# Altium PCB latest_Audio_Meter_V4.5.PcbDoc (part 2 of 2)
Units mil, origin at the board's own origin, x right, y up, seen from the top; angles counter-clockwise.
Board outline 2756.14 x 2519.69 mil, 2 copper layers (Top Layer, Bottom Layer), stack 57.087 mil thick; 115 components, 61 nets, 352 pads, 1177 vias.
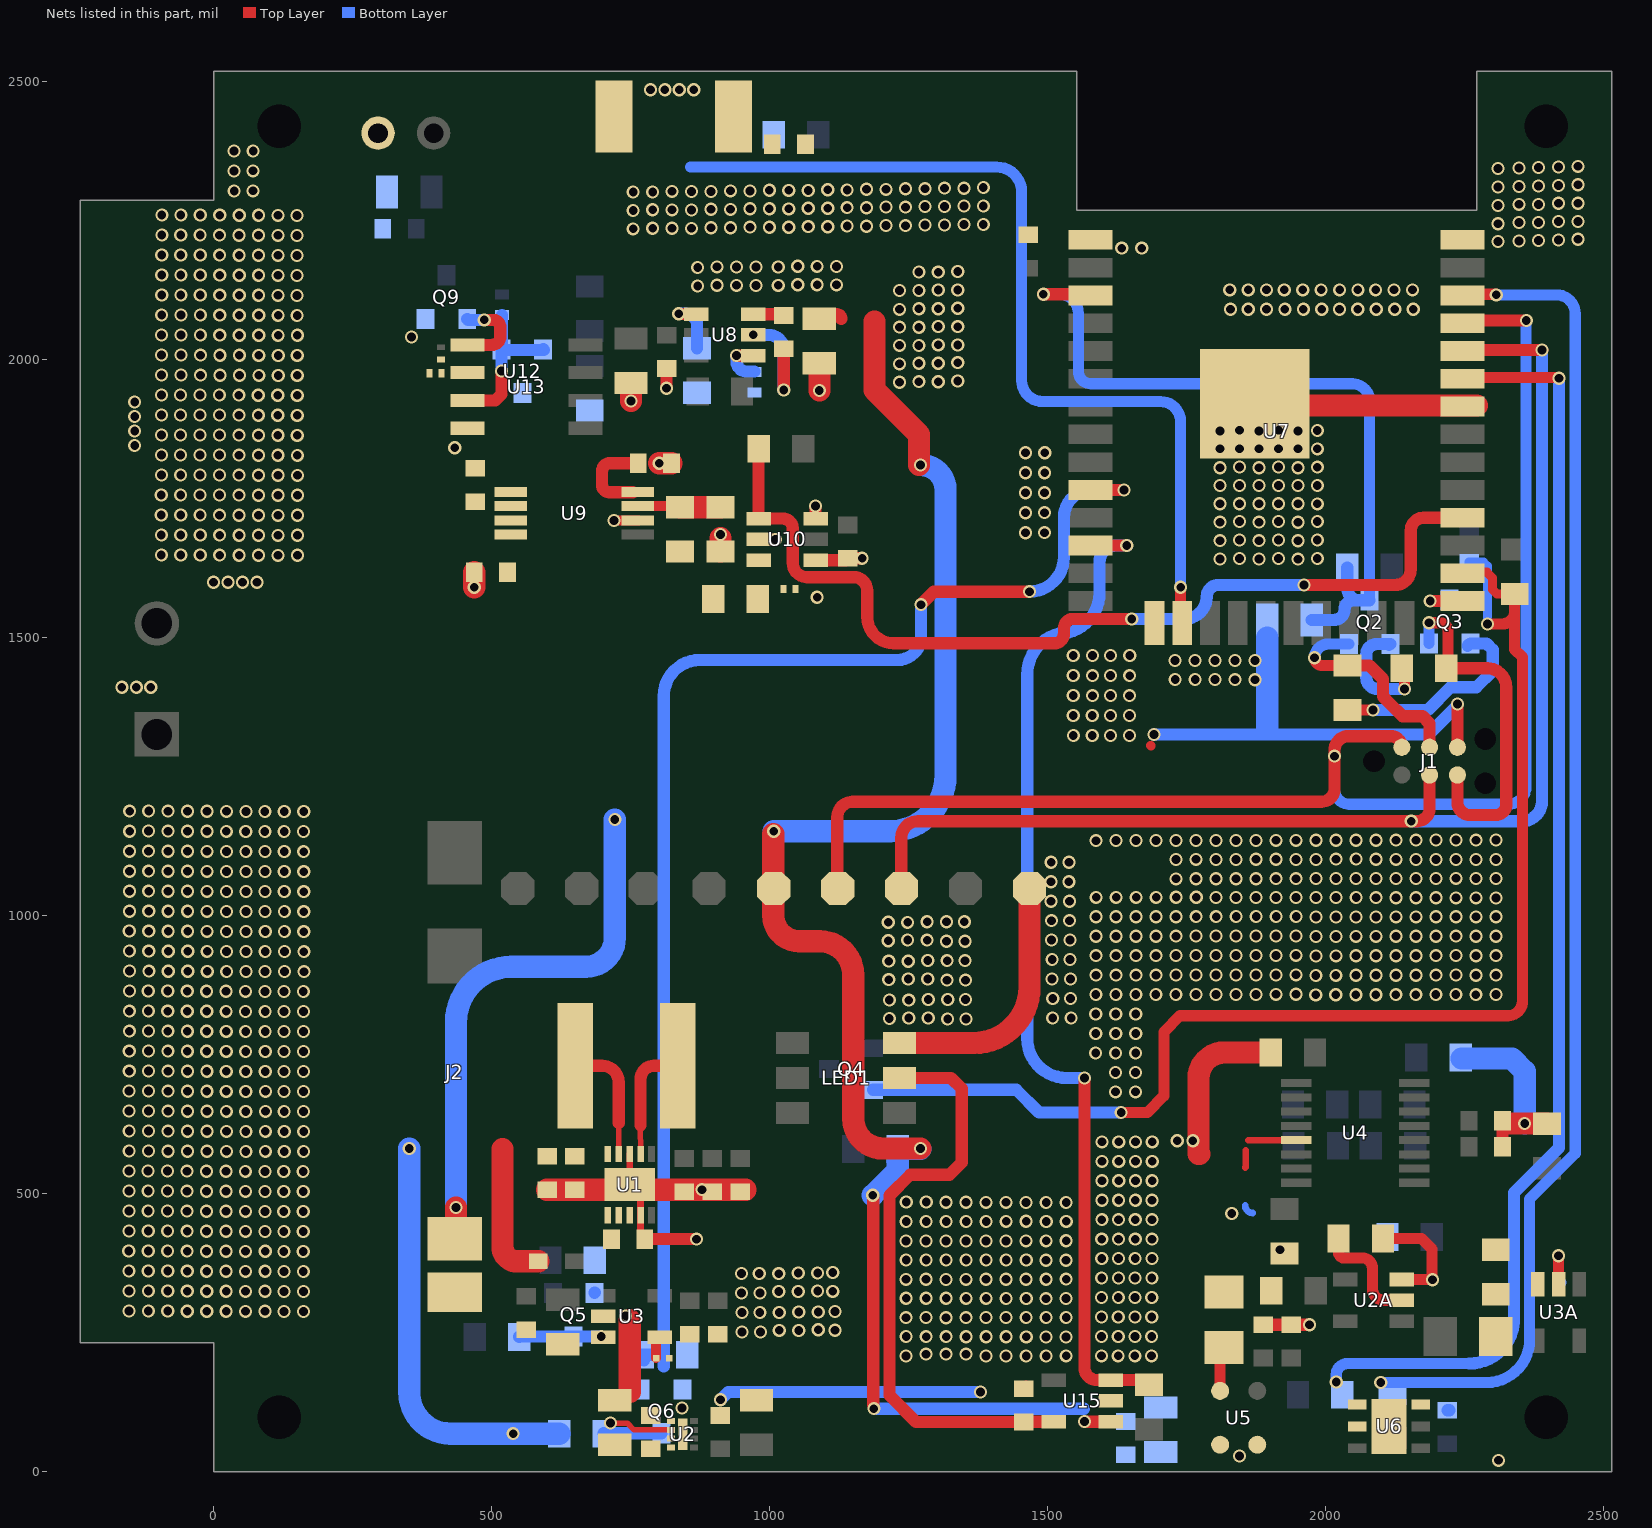
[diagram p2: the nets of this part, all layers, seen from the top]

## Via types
v1: diameter 23.62, hole 15.75, Top Layer to Bottom Layer, 917 vias
v2: diameter 23.62, hole 15.75, Top Layer to Bottom Layer, tented both sides, 260 vias

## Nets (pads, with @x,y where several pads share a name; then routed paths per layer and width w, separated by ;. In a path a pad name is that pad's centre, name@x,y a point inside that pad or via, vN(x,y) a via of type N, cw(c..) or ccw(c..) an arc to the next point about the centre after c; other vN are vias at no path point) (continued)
CLED#: C76.2 Q4.2 R56.2 U7.26 | length 2418
  Top Layer w8: R56.2@2323,1579 R56.2@2341,1579
  Top Layer w12: R56.2@2323,1579 R56.2@2323,1588
  Top Layer w16: U7.26@2242,1618 2291,1618 2301,1608 2301,1587 2309,1579 R56.2@2323,1579
  Top Layer w20: v1(1633,646) 1680,646 1710,676 1710,791 1739,820 2329,820 ccw(c2329,846) 2355,846 2355,1465 2341,1479 2341,1546.94 ; U7.26@2242,1618 ccw(c2243,1618) U7.26@2243,1617 ; v1(2292,1525) 2319.06,1525 ccw(c2319.06,1546.94) 2341,1546.94 ; R56.2@2341,1579 2341,1546.94
  Bottom Layer w16: C76.2@2259,1636 2285,1636 2292,1629 v1(2292,1525)
  Bottom Layer w22: Q4.2@1186.37,686.6 1444.4,686.6 1485,646 v1(1633,646)
DTR: J1.5 Q3.2 RC2.2 | length 644.9
  Top Layer w20: v1(2187,1527) 2206.76,1527 cw(c2206.76,1512.76) 2221,1512.76 RC2.2@2221,1447
  Top Layer w22: RC2.2@2218,1445 2291.86,1445 cw(c2291.86,1410.86) 2326,1410.86 2326,1200.35 cw(c2306.65,1200.35) 2306.65,1181 2260.94,1181 cw(c2260.94,1203.94) 2238,1203.94 J1.5@2238,1253
  Bottom Layer w20: Q3.2@2186.6,1489.63 2186.6,1527 v1(2187,1527)
EN#: Q6.3 R4#.1 U2.6 | length 224.2
  Top Layer w10: v1@710.88,86.12 710,87 v1(714,87) 744.31,87 756.44,74.87 U2.6@823.33,74.87
  Bottom Layer w10: R4#.1@702,68 R4#.1@702,68.63
  Bottom Layer w22: R4#.1@702,68.63 Q6.3@806,68.63
ENABLE: C78.1 Q2.3 R43.1 U7.3 | length 1374.9
  Top Layer w22: v1(1493,2118) U7.3@1572.71,2118
  Bottom Layer w20: v1(1493,2118) 1522.14,2118 cw(c1522.14,2084.14) 1556,2084.14 1556,1979.94 ccw(c1578.94,1979.94) 1578.94,1957 2049,1957 cw(c2049,1926) 2080,1926 Q2.3@2080,1567.37 ; 2012,1532 2015.9,1532
  Bottom Layer w22: C78.1@1976,1532 2012,1532 ; 2015.9,1532 ccw(c2015.9,1551.1) 2035,1551.1 cw(c2051.27,1551.1) 2051.27,1567.37 2060.94,1567.37 ; R43.1@2040,1626.44 2040,1588.31 ccw(c2060.94,1588.31) 2060.94,1567.37 ; Q2.3@2080,1567.37 2060.94,1567.37
GND: C1.2 C2.2 C3.2 C4.2 C7.2 C10.2 C11.2 C12.2 C13.2 C16.2 C17.2 C18.2 C19.2 C22.2 C25.2 C26.2 C27.2 C28.2 C29.2 C33.2 C34.2 C35.2 C37.2 C38.2 C40.2 C41.2 C78.2 C79.2 C80.2 C81.2 C82.2 C85.2 C#3.2 C#4.2 C#5.2 J1.6 J2.4 J5.2 LED1.6 P5.1 pad.MH2 pad.MH3 Q5.2 Q6.2 R3.2 R8.1 R10.1 R12.1 R14.1 R28.1 R29.1 R32.2 R33.2 R35.2 R36.2 R38.1 R39.2 R42.2 SW2.2 U1.3 U1.9 U1.11 U2.5 U2.9 U2A.2 U3.2 U3A.2 U4.5 U5.2 U5.3 U6.2 U6.7 U7.1 U7.15 U7.32 U7.38 U7.39 U8.5 U9.2 U9.5 U10.2 U10.4 U10.6 U12.3 U13.4 U15.2 | length 4682.1
  Top Layer w12: U1.3@748.63,571.24 748.63,532.37 768.31,512.69 768.31,507 U1.11@768.31,503 ; C10.2@768.31,420.69 U1.9@768.31,461 U1.11@768.31,502 ; 1856,547 ccw(c1856,548) 1857,548 1857,578 ; 1862,596.2 U4.5@1947.75,596.2 ; v1@2353.05,626 ccw(c2334,637) v1@2356,637
  Top Layer w16: 1686,1306 cw(c1686,1305) 1687,1305
  Top Layer w18: v1(720.44,1711) U9.2@764.97,1711
  Top Layer w20: R3.2@2024,419 2024,395 ccw(c2035,395) 2035,384 2067,384 cw(c2067,366) 2085,366 2085,329 ccw(c2106,329) 2106,308 U2A.2@2138.18,308 ; U3A.2@2420,337.18 v1(2420,388)
  Top Layer w22: U1.11@763.31,507 ccw(c767.31,507) 767.31,503 U1.11@768.21,503 ; U1.11@768.31,502 ccw(c763.31,502) U1.11@768.21,503 ; U1.11@768.31,503 U1.11@768.21,503 ; C10.2@773,418 C10.2@776,418 v1(869,418) ; v1(815,1949) C17.2@815,1984.57 ; C12.2@896,502 cw(c897,502) C12.2@897,503 ; C37.2@905,245 cw(c907,245) C37.2@907,247 ; v1(971.18,2045) U8.5@980.85,2045 ; U10.2@980.82,1677 v1(1011,1677) ; v1(1026,1946) C19.2@1026,2020 ; v1(1083,1737) 1083.18,1736.82 U10.6@1083.18,1714.4 ; U10.4@1083.18,1639.6 1137.6,1639.6 ccw(c1137.6,1643) C85.2@1141,1643 v1@1164,1643 ; C#3.2@1458,149 C#3.2@1462.02,153.02 ; C3.2@1889,264 C4.2@1939,264 v1(1972,264) ; U6.7@2115,46.77 U6.7@2115,81 ; J1.6@2238,1303 v1(2238,1381) ; C1.2@2319,584 C2.2@2319,631
  Top Layer w40: v1(469,1591) C79.2@469,1618 ; C11.2@600,507 C40.2@650,507 U1.11@763.31,507 ; C27.2@749,143 v1@749,272 ; v1(751,1926) C16.2@751,1958.57 ; U1.11@768.31,507 v1(879,507) C13.2@957,507 ; v1(802,1814) R39.2@824,1814 ; R38.1@912,1655 v1@912,1679 ; v1(1090,1945) C18.2@1090,1994 ; LED1.6@1234.46,770.99 1368,770.99 ccw(c1368,870.99) 1468,870.99 P5.1@1468,1049 ; 1774,571 cw(c1774,573) 1772,573 1772,707 cw(c1819,707) 1819,754 R8.1@1902,754 ; U7.39@1868.35,1923.31 ccw(c1873.67,1923.31) 1873.67,1918 U7.32@2273,1918 ; C2.2@2324,626 2353.05,626 v1(2359,626) R12.1@2399,626
  Bottom Layer w12: 1856,479 ccw(c1870,479) 1870,465
  Bottom Layer w20: 2420,344 ccw(c2424,344) 2424,340
  Bottom Layer w22: Q5.2@685.4,321.37 Q5.2@686,321.97 ; v1(912,129) 926,143 v1(1380,143) ; v1(971.18,2045) 998.77,2045 cw(c998.77,2017.78) 1026,2017.78 v1(1026,1946) ; v1(1692,1326) 2186,1326 2238,1378 v1(2238,1381) ; C7.2@2220,110 C7.2@2224,110 ; R10.1@2244,745 ccw(c2246,745) R10.1@2246,743
  Bottom Layer w40: 1896,1337 1896,1500 ; R10.1@2246,743 2336,743 2359,720 v1(2359,626)
  other v1: 2312,20 1846,28 843,114 1246.02,207.67 1390.02,207.79 1426.02,207.79 1462.02,207.9 1498.02,207.9 1534.02,208.01 1597.44,208 1627.55,208 1657.66,208 1687.77,208 1282,211 1318,211 1354,211 1354.13,242.45 1390.13,242.45 1426.13,242.34 1462.13,242.23 1497.9,241.89 1533.9,242.01 1246.13,242.67 1282.13,242.56 1318.13,242.56 1597.55,243 1627.66,243 1657.77,243 1687.89,243 950.78,251 984,251 1017.89,253.89 1052.89,253.78 1118,254 1087.89,254.89 1246.01,276.67 1282.01,276.78 1318.01,276.56 1354.01,276.67 1390.01,276.78 1426.01,276.78 1462.01,276.89 1498.01,276.89 1534.01,277.01 1597.66,278 1627.77,278 1657.89,278 1688,278 741,280 950.89,286 982.89,286 1017.89,285.89 1052.89,287 1087.89,286.89 1118,288 1354.12,311.45 1390.12,311.45 1426.12,311.34 1462.12,311.23 1497.89,310.89 1533.89,311 1246.12,311.67 1282.12,311.56 1318.12,311.56 1597.77,313 1627.89,313 1658,313 1688.11,313 949.78,321 983,321 1016.89,323.89 1051.89,323.78 1114,324 1086.89,324.89 1246.01,345.67 1282.01,345.78 1318.01,345.56 1354.01,345.67 1390.01,345.78 1426.01,345.78 1462.01,345.89 1498.01,345.89 1534.01,346 1597.89,348 1628,348 1658.11,348 1688.22,348 949.89,356 981.89,356 1016.89,355.89 1051.89,357 1086.89,356.89 1114,358 1354.12,380.45 1390.12,380.45 1426.12,380.33 1462.12,380.22 1497.89,379.89 1533.89,380 1246.12,380.67 1282.12,380.56 1318.12,380.56 1598,383 1628.11,383 1658.22,383 1688.33,383 1919,399 1246,414.67 1282,414.78 1318,414.55 1354,414.67 1390,414.78 1426,414.78 1462,414.89 1498,414.89 1534,415 1598.11,418 1628.22,418 1658.33,418 1688.44,418 1246.11,449.67 1282.11,449.78 1318.11,449.78 1354.11,449.89 1390.11,449.89 1426.11,450 1462.11,450.11 1498.11,449.89 1534.11,450 1598.22,453 1628.33,453 1658.44,453 1688.55,453 1832,464 1317.99,484.44 1353.99,484.33 1389.99,484.22 1425.99,484.22 1461.99,484.11 1497.99,484.11 1533.99,484 1246.22,484.67 1282.22,484.78 1598.33,488 1628.44,488 1658.55,488 1688.67,488 1598.44,523 1628.55,523 1658.67,523 1688.78,523 1598.55,558 1628.67,558 1658.78,558 1688.89,558 1598.67,593 1628.78,593 1658.89,593 1689,593 1734,595 1762,595 1622.89,683 1658.89,683 1623,718 1659,718 1587.11,753 1623.11,753 1659.11,753 1587.22,788 1623.22,788 1659.22,788 1320.78,814 1354,814 1215.89,814.89 1250.89,816 1285.89,815.89 1509.78,816 1543,816 1587.33,823 1623.33,823 1659.33,823 1215.89,848.11 1250.89,848 1285.89,849.11 1320.89,849 1352.89,849 1509.89,851 1541.89,851 1587.44,858 1623.44,858 1659.44,858 1695.44,858 1731.44,858.11 1767.44,858.22 1803.44,858.22 1839.44,858.33 1875.44,858.33 1911.44,858.45 1983.22,857.55 2019.22,857.67 2055.22,857.78 2091.22,857.78 2127.22,857.89 2163.22,857.89 2199.22,858 2235.22,858.11 2271.22,857.89 2307.22,858 1947.44,858.56 1319.78,884 1353,884 1214.89,884.89 1249.89,886 1284.89,885.89 1508.78,886 1542,886 1587.55,893 1623.55,893 1659.55,893 1695.55,893 1731.55,893.11 1767.55,893.22 1803.55,893.22 1839.55,893.33 1875.55,893.33 1911.55,893.45 1983.33,892.55 2019.33,892.67 2055.33,892.78 2091.33,892.78 2127.33,892.89 2163.33,892.89 2199.33,893 2235.33,893.11 2271.33,892.89 2307.33,893 1947.55,893.56 1214.89,918.11 1249.89,918 1284.89,919.11 1319.89,919 1351.89,919 1508.89,921 1540.89,921 1587.67,928 1623.67,928 1659.67,928 1695.67,928 1731.67,928.11 1767.67,928.22 1803.67,928.22 1839.67,928.33 1875.67,928.33 1911.67,928.45 1983.44,927.55 2019.44,927.67 2055.44,927.78 2091.44,927.78 2127.44,927.89 2163.44,927.89 2199.44,928 2235.44,928.11 2271.44,927.89 2307.44,928 1947.67,928.56 1318.78,954 1352,954 1213.89,954.89 1248.89,956 1283.89,955.89 1507.78,956 1541,956 1587.78,963 1623.78,963 1659.78,963 1695.78,963 1731.78,963.11 1767.78,963.22 1803.78,963.22 1839.78,963.33 1875.78,963.33 1911.78,963.45 1983.55,962.55 2019.55,962.67 2055.55,962.78 2091.55,962.78 2127.55,962.89 2163.55,962.89 2199.55,963 2235.55,963.11 2271.55,962.89 2307.55,963 1947.78,963.56 1213.89,988.11 1248.89,988 1283.89,989.11 1318.89,989 1350.89,989 1507.89,991 1539.89,991 1587.89,998 1623.89,998 1659.89,998 1695.89,998 1731.89,998.11 1767.89,998.22 1803.89,998.22 1839.89,998.33 1875.89,998.33 1911.89,998.45 1983.66,997.55 2019.66,997.67 2055.66,997.78 2091.66,997.78 2127.66,997.89 2163.66,997.89 2199.66,998 2235.66,998.11 2271.66,997.89 2307.66,998 1947.89,998.56 1506.78,1026 1540,1026 2091.54,1032.44 2127.54,1032.33 2163.54,1032.22 2199.54,1032.22 2235.54,1032.11 2271.54,1032.11 2307.54,1032 1588,1033 1624,1033 1660,1033 1696,1033 1732,1033.11 1768,1033.22 1803.77,1032.89 1839.77,1032.78 1875.77,1032.67 1911.77,1032.67 1947.77,1032.55 1983.77,1032.55 2019.77,1032.67 2055.77,1032.78 1506.89,1061 1538.89,1061 1731.66,1066.22 1767.66,1066.33 1803.66,1066.33 1839.66,1066.44 1875.66,1066.44 1911.66,1066.55 1947.66,1066.55 1983.66,1066.66 2019.66,1066.66 2055.66,1066.77 2091.66,1066.77 2127.66,1066.89 2163.66,1066.89 2199.66,1067 2235.66,1067.11 2271.66,1066.89 2307.66,1067 1507,1096 1539,1096 1731.77,1101.22 1767.77,1101.33 1803.54,1100.99 1839.54,1100.88 1875.77,1101.44 1947.54,1101.22 1983.54,1101.11 2091.54,1101.44 2127.54,1101.33 2163.54,1101.22 2199.54,1101.22 2235.54,1101.11 2271.54,1101.11 2307.54,1100.99 1911.77,1101.55 2019.77,1101.66 2055.77,1101.77 1587.65,1134.99 1623.65,1135.1 1659.65,1135.1 1695.65,1135.22 1731.65,1135.22 1767.65,1135.33 1803.65,1135.33 1839.65,1135.44 1875.65,1135.44 1911.65,1135.55 1947.65,1135.55 1983.65,1135.66 2019.65,1135.66 2055.65,1135.77 2091.65,1135.77 2127.65,1135.88 2163.65,1135.88 2199.65,1135.99 2235.65,1136.11 2271.65,1135.88 2307.65,1135.99 1547,1324 1581,1324.12 1614,1324 1648,1324.12 1546.89,1360 1580.89,1360.12 1613.89,1360 1647.89,1360.12 1546.89,1396 1581.22,1395.89 1613.89,1396 1648.22,1395.89 -165,1411 -139,1411 -113,1411 1730.12,1425 1766.12,1425.11 1801.89,1424.78 1837.89,1424.67 1873.89,1424.56 1546.78,1432 1581.33,1431.89 1613.78,1432 1648.33,1431.89 1730,1459 1766,1459.11 1802,1459.11 1838,1459.22 1874,1459.22 1546.78,1468 1581.44,1467.89 1613.78,1468 1648.44,1467.89 1086,1573 0,1600 26,1600 52,1600 78,1600 1951,1641.44 1811,1641.55 1881,1641.55 1167,1643 1846,1642.67 1916,1642.67 1986,1642.55 81,1648.44 116,1648.33 151,1648.44 -94,1649 -59,1648.89 -24,1648.78 11,1648.67 46,1648.55 1811,1674.78 1881,1674.78 1951,1674.67 1846,1675.89 1916,1675.89 1986,1675.78 81,1684.44 116,1684.33 151,1684.44 -94,1685 -59,1684.89 -24,1684.78 11,1684.67 46,1684.55 912,1686 1461,1689 1495,1689.12 1811,1708 1881,1708 1951,1707.89 1846,1709.11 1916,1709.11 1986,1709 80.89,1720.44 115.89,1720.33 151.11,1720.44 -94.11,1721 -59.11,1720.89 -24.11,1720.78 10.89,1720.67 45.89,1720.55 1460.89,1725 1494.89,1725.12 1811,1741.22 1846,1741.11 1881,1741.22 1916,1741.11 1951,1741.11 1986,1741 80.78,1756.44 115.78,1756.33 151.22,1756.44 -94.22,1757 -59.22,1756.89 -24.22,1756.78 10.78,1756.67 45.78,1756.55 1460.89,1761 1495.22,1760.89 1811,1774 1846,1773.89 1881,1774 1916,1773.89 1951,1773.89 1986,1773.78 80.78,1792.44 115.78,1792.33 150.89,1792.22 -93.89,1792.77 -59.22,1792.89 -24.22,1792.78 10.78,1792.67 45.78,1792.55 1460.78,1797 1495.33,1796.89 1811,1806 1881,1806 1951,1805.89 1846,1807.11 1916,1807.11 1986,1807 80.67,1828.44 115.67,1828.33 150.78,1828.22 -93.78,1828.77 -59.33,1828.89 -24.33,1828.78 10.67,1828.67 45.67,1828.55 1460.78,1833 1495.44,1832.89 1811,1840.13 1846,1840.02 1881,1840.13 1916,1840.02 1951,1840.02 1986,1839.91 434,1842 -142,1846 80.67,1864.44 115.67,1864.33 150.67,1864.22 -93.67,1864.77 -59.33,1864.89 -24.33,1864.78 10.67,1864.67 45.67,1864.55 -142,1872 1811,1872.13 1881,1872.13 1951,1872.02 1846,1873.24 1916,1873.24 1986,1873.13 -142,1898 80.55,1900.44 115.55,1900.33 150.67,1900.22 -93.67,1900.77 -59.45,1900.89 -24.45,1900.78 10.55,1900.67 45.55,1900.55 -142,1924 80.44,1936.44 115.44,1936.33 150.55,1936.22 -93.55,1936.77 -59.56,1936.89 -24.56,1936.78 10.44,1936.67 45.44,1936.55 1234,1959.67 1269,1960.78 1304,1960.67 1339,1961.78 11.45,1972.44 46.45,1972.33 81.45,1972.22 116.45,1972.1 150.55,1972.22 -93.55,1972.77 -58.55,1972.66 -23.55,1972.55 1234,1992.89 1269,1994 1304,1993.89 1339,1995 11.33,2008.44 46.33,2008.33 81.33,2008.22 116.33,2008.1 150.67,2008.22 -93.67,2008.77 -58.67,2008.66 -23.67,2008.55 1234,2026.11 1269,2026 1304,2027.11 1339,2027 11.22,2044.44 46.22,2044.33 81.22,2044.22 116.22,2044.1 150.78,2044.22 -93.78,2044.77 -58.78,2044.66 -23.78,2044.55 1234,2058.89 1269,2058.78 1304,2059.89 1339,2059.78 11.22,2080.44 46.22,2080.33 81.22,2080.22 116.22,2080.1 150.44,2079.99 -93.44,2080.54 -58.78,2080.66 -23.78,2080.55 1234,2090.89 1829.55,2091 1861.55,2091 1894.33,2091 1927.55,2091 1960.78,2091 1994,2091 2026,2091 2058.78,2091 2092,2091 2125.22,2091 2158.45,2091 1269,2092 1304,2091.89 1339,2093 11.11,2116.44 46.11,2116.33 81.11,2116.22 116.11,2116.1 150.33,2115.99 -93.33,2116.54 -58.89,2116.66 -23.89,2116.55 1234,2124.89 1269,2124.78 1304,2125.89 1339,2125.78 1828.44,2126 1861.67,2126 1894.44,2126 1926.44,2126 1959.67,2126 1992.89,2126 2026.11,2126 2058.89,2126 2090.89,2126 2124.11,2126 2157.33,2126 871,2133.11 906,2134.22 941,2134.11 976,2134 1016,2134.11 1051,2135.22 1086,2135.11 1121,2135 11.11,2152.44 46.11,2152.33 81.11,2152.22 116.11,2152.1 150.22,2151.99 -93.22,2152.54 -58.89,2152.66 -23.89,2152.55 1269,2158 1304,2157.89 1339,2159 871,2166.33 906,2167.45 941,2167.33 976,2167.22 1016,2167.33 1051,2168.45 1086,2168.33 1121,2168.22 11,2188.44 46,2188.33 81,2188.22 116,2188.1 150.22,2187.99 -93.22,2188.54 -59,2188.66 -24,2188.55 1634,2201 1670,2201 2311,2213 2349,2213.89 2384,2215 2420,2215.89 2455,2217 10.89,2224.44 45.89,2224.33 80.89,2224.22 115.89,2224.1 150.11,2223.99 -93.11,2224.54 -59.11,2224.66 -24.11,2224.55 755,2235.78 790,2236.89 825,2236.78 860,2236.67 895,2237.78 930,2237.67 965,2238.78 1000,2238.67 1035,2238.55 1070,2239.67 1105,2239.55 1140,2240.67 1175,2240.55 1210,2241.67 1245,2241.55 1280,2242.67 1315,2242.55 1350,2243.67 1385,2243.55 2311,2245 2349,2247.11 2384,2247 2420,2249.11 2455,2249 11.11,2260.44 46.11,2260.33 81.11,2260.22 116.11,2260.1 150.11,2259.99 -93.11,2260.54 -58.89,2260.66 -23.89,2260.55 755,2269 790,2270.11 825,2270 860,2269.89 895,2271 930,2270.89 965,2272 1000,2271.89 1035,2271.78 1070,2272.89 1105,2272.78 1140,2273.89 1175,2273.78 1210,2274.89 1245,2274.78 1280,2275.89 1315,2275.78 1350,2276.89 1385,2276.78 2311,2277.78 2349,2279.89 2384,2279.78 2420,2281.89 2455,2281.78 755,2302.22 790,2302.11 825,2303.22 860,2303.11 895,2303 37,2304 71,2304.12 930,2304.11 965,2304 1000,2305.11 1035,2305 1070,2304.89 1105,2306 1140,2305.89 1175,2307 1210,2306.89 1245,2308 1280,2307.89 1315,2309 1350,2308.89 1385,2310 2311,2311 2349,2311.89 2384,2313 2420,2313.89 2455,2315 36.89,2340 70.89,2340.12 2311,2344.22 2349,2345.11 2384,2346.22 2420,2347.11 2455,2348.22 36.89,2376 71.22,2375.89
  other v2: -82.34,288.46 -47.34,288.35 -12.34,288.24 22.66,288.13 57.66,288.02 92.66,288.13 126.66,287.79 161.66,287.68 -152.34,288.68 -117.34,288.57 -82.34,324.46 -47.34,324.35 -12.34,324.24 22.66,324.13 57.66,324.02 92.66,324.13 126.66,323.79 161.66,323.68 -152.34,324.68 -117.34,324.57 -82.45,360.46 -47.45,360.35 -12.45,360.24 22.55,360.13 57.55,360.02 92.77,360.13 126.55,359.79 161.55,359.68 -152.45,360.68 -117.45,360.57 -82.56,396.46 -47.56,396.35 -12.56,396.24 22.44,396.13 57.44,396.02 92.89,396.13 126.44,395.79 161.44,395.68 -152.56,396.68 -117.56,396.57 -152.23,432.46 -82.56,432.46 -47.56,432.35 -12.56,432.24 22.44,432.13 57.44,432.02 92.55,431.9 126.44,431.79 161.44,431.68 -117.56,432.57 -152.11,468.46 -82.67,468.46 -47.67,468.35 -12.67,468.24 22.33,468.13 57.33,468.02 92.44,467.9 126.33,467.79 161.33,467.68 -117.67,468.57 -152,504.46 -82.67,504.46 -47.67,504.35 -12.67,504.24 22.33,504.13 57.33,504.02 92.33,503.9 126.33,503.79 161.33,503.68 -117.67,504.57 -152,540.46 -82.78,540.46 -47.78,540.35 -12.78,540.24 22.22,540.13 57.22,540.02 92.33,539.9 126.22,539.79 161.22,539.68 -117.78,540.57 162.11,575.45 -151.89,576.46 -116.89,576.34 -81.89,576.23 -46.89,576.12 -11.89,576.01 23.11,575.9 58.11,575.79 93.11,575.9 127.11,575.56 162.11,611.45 -151.89,612.46 -116.89,612.34 -81.89,612.23 -46.89,612.12 -11.89,612.01 23.11,611.9 58.11,611.79 93.11,611.9 127.11,611.56 161.99,647.45 -152,648.46 -117,648.34 -82,648.23 -47,648.12 -12,648.01 23,647.9 58,647.79 93.22,647.9 126.99,647.56 161.88,683.45 -152.11,684.46 -117.11,684.34 -82.11,684.23 -47.11,684.12 -12.11,684.01 22.89,683.9 57.89,683.79 93.33,683.9 126.88,683.56 161.88,719.45 -151.78,720.23 -117.11,720.34 -82.11,720.23 -47.11,720.12 -12.11,720.01 22.89,719.9 57.89,719.79 93,719.67 126.88,719.56 161.77,755.45 -151.67,756.23 -117.23,756.34 -82.23,756.23 -47.23,756.12 -12.23,756.01 22.77,755.9 57.77,755.79 92.89,755.67 126.77,755.56 161.77,791.45 -151.56,792.23 -117.23,792.34 -82.23,792.23 -47.23,792.12 -12.23,792.01 22.77,791.9 57.77,791.79 92.77,791.67 126.77,791.56 161.66,827.45 -151.56,828.23 -117.34,828.34 -82.34,828.23 -47.34,828.12 -12.34,828.01 22.66,827.9 57.66,827.79 92.77,827.67 126.66,827.56 161.55,863.45 -151.45,864.23 -117.45,864.34 -82.45,864.23 -47.45,864.12 -12.45,864.01 22.55,863.9 57.55,863.79 92.66,863.67 126.55,863.56 127.55,899.33 162.55,899.22 -151.45,900.23 -116.45,900.12 -81.45,900.01 -46.45,899.89 -11.45,899.78 23.55,899.67 58.55,899.56 92.66,899.67 127.44,935.33 162.44,935.22 -151.56,936.23 -116.56,936.12 -81.56,936.01 -46.56,935.89 -11.56,935.78 23.44,935.67 58.44,935.56 92.77,935.67 127.33,971.33 162.33,971.22 -151.67,972.23 -116.67,972.12 -81.67,972.01 -46.67,971.89 -11.67,971.78 23.33,971.67 58.33,971.56 92.89,971.67 92.55,1007.44 127.33,1007.33 162.33,1007.22 -151.33,1008 -116.67,1008.12 -81.67,1008.01 -46.67,1007.89 -11.67,1007.78 23.33,1007.67 58.33,1007.56 92.44,1043.44 127.22,1043.33 162.22,1043.22 -151.22,1044 -116.78,1044.12 -81.78,1044.01 -46.78,1043.89 -11.78,1043.78 23.22,1043.67 58.22,1043.56 92.33,1079.44 127.22,1079.33 162.22,1079.22 -151.11,1080 -116.78,1080.12 -81.78,1080.01 -46.78,1079.89 -11.78,1079.78 23.22,1079.67 58.22,1079.56 92.33,1115.44 127.11,1115.33 162.11,1115.22 -151.11,1116 -116.89,1116.12 -81.89,1116.01 -46.89,1115.89 -11.89,1115.78 23.11,1115.67 58.11,1115.56 92.22,1151.44 126.99,1151.33 161.99,1151.22 -151,1152 -117,1152.12 -82,1152.01 -47,1151.89 -12,1151.78 23,1151.67 58,1151.56 92.22,1187.44 127.22,1187.33 162.22,1187.22 -151,1188 -116.78,1188.12 -81.78,1188.01 -46.78,1187.89 -11.78,1187.78 23.22,1187.67 58.22,1187.56
ILIM#: R39.1 U9.4 | length 160.7
  Top Layer w22: U9.4@754.12,1762 712,1762 cw(c712,1775) 699,1775 699,1800.34 cw(c712.66,1800.34) 712.66,1814 R39.1@764,1814
IN+: R30.1 U12.1 U12.2 U13.3 | length 286.9
  Top Layer w22: U13.3@456.7,1927 507,1927 518,1938 v1(518,1980)
  Bottom Layer w22: v1(518,1980) 518.2,1980.2 U12.1@518.2,2019 ; R30.1@519,2081 519,2019.8 U12.1@518.2,2019 ; U12.2@593,2019 594,2018 519.2,2018 U12.1@518.2,2019
IN-: R31.1 R32.1 U13.2 | length 2
  Top Layer w12: U13.2@456.7,1977 U13.2@458.7,1977
IO_0: Q3.3 U7.25 | length 104.5
  Top Layer w20: U7.25@2242,1568 2244,1566 U7.25@2249,1561
  Top Layer w22: v1(2189,1566) 2244,1566 U7.25@2247.29,1566
  Bottom Layer w22: v1(2189,1566) 2221.63,1566 ccw(c2221.63,1568.37) Q3.3@2224,1568.37
ISET: R28.2 U8.4 | length 83.5
  Top Layer w22: v1@941,2007.6 U8.4@971.18,2007.6
  Bottom Layer w22: v1(941,2008) 941,1996.93 ccw(c958.93,1996.93) 958.93,1979 R28.2@973,1979
LED#: R83.2 U7.12 U15.3 | length 1855.4
  Top Layer w22: v1(1567,708) 1567,187.1 ccw(c1589.7,187.1) 1589.7,164.4 U15.3@1614.18,164.4 1674.6,164.4 cw(c1674.6,156) R83.2@1683,156 R83.2@1682.4,155.4 ; U7.12@1578,1666 v1(1643,1666)
  Bottom Layer w22: v1(1567,708) 1535,708 cw(c1535,779) 1464,779 1464,1434 cw(c1540,1434) 1521.15,1507.62 ccw(c1521.15,1580.48) 1594,1580.48 1594,1636 cw(c1624,1636) 1624,1666 v1(1643,1666)
NetC8_2: C8.2 R1.1
NetC9_2: C9.2 R6.2
NetC33_1: C33.1 U3.4 | length 30.6
  Top Layer w18: C33.1@796.19,204 U3.4@796.19,234.61
NetL1_1: L1.1 U1.4 | length 224.4
  Top Layer w10: U1.4@728.94,571.24 728.94,627
  Top Layer w22: L1.1@650.48,730 698.98,730 cw(c698.98,700) 729,700 729,627
NetL1_2: L1.2 U1.2 | length 215.7
  Top Layer w10: 768,623 U1.2@768.32,571.24
  Top Layer w22: 768,623 768.32,705.96 cw(c792.36,705.96) 792.36,730 L1.2@835.52,730
NetQ2_1: Q2.1 RC2.1 | length 219.2
  Top Layer w20: RC2.1@2138,1445 2143,1440 v1(2143,1408)
  Bottom Layer w20: Q2.1@2115,1486.23 cw(c2117.4,1486.23) Q2.1@2117.4,1488.63
  Bottom Layer w22: Q2.1@2117.4,1488.63 2092.63,1488.63 ccw(c2092.63,1470) 2074,1470 2074,1428.29 ccw(c2094.29,1428.29) 2094.29,1408 v1(2143,1408)
NetQ3_1: Q3.1 RC3.1 | length 393
  Top Layer w20: RC3.1@2047,1363 cw(c2047,1370) RC3.1@2040,1370 v1(2086,1370)
  Bottom Layer w20: Q3.1@2256,1484.23 cw(c2261.4,1484.23) Q3.1@2261.4,1489.63
  Bottom Layer w22: v1(2086,1370) 2184.84,1370 2225.65,1410.81 2271.96,1410.81 2301.5,1440.35 2301.5,1478.5 2290.37,1489.63 Q3.1@2261.4,1489.63
NetQ9_1: Q9.1 U13.1 | length 152.4
  Top Layer w22: U13.1@456.7,2027 501,2027 ccw(c501,2042) 516,2042 516,2058.52 ccw(c502.52,2058.52) 502.52,2072 v1(487,2072)
  Bottom Layer w22: Q9.1@456.4,2073.63 458.03,2072 v1(487,2072)
NetR2_1: R2.1 R3.1 U2A.3 | length 205.7
  Top Layer w20: R3.1@2104,419 2173,419 2192,400 v1@2192,345.4 ; U2A.3@2138.18,345.4 v1@2192,345.4 ; v1(2193,345) 2192,345 v1@2192,345.4
NetR6_1: R6.1 U3A.3
ON/OFF#: Q5.3 R1#.1 U3.3 | length 148.3
  Bottom Layer w22: R1#.1@550,242 550,242.63 Q5.3@648,242.63 v1(697.63,242.63)
OUT_MIC: C8.1 U5.4 | length 85
  Top Layer w20: U5.4@1811.07,145 1811.07,208.07 cw(c1825,208.07) C8.1@1825,222
P_D: C10.1 U1.6 U1.7 U1.8
RTS: J1.4 Q2.2 RC3.2 | length 395.5
  Top Layer w20: v1(1981,1464) ccw(c1995,1464) 1995,1450 RC3.2@2040,1450
  Top Layer w22: RC3.2@2040,1450 2080,1450 2104,1426 2104,1394.16 2115.81,1382.35 2115.81,1382.19 2139,1359 2175,1359 2188,1346 J1.4@2188,1303
  Bottom Layer w20: v1(1981,1464) cw(c2005.63,1464) 2005.63,1488.63 Q2.2@2042.6,1488.63
RX: J1.3 P7.1 U7.34 | length 2348.7
  Top Layer w22: P7.1@1237.5,1049 1237.5,1140.28 cw(c1267.23,1140.28) 1267.23,1170 v1(2155,1170) 2165.06,1170 ccw(c2165.06,1192.94) 2188,1192.94 J1.3@2188,1253 ; U7.34@2242,2018 v1(2390,2018) v1@2391,2018
  Bottom Layer w22: v1(2155,1170) 2354.58,1170 ccw(c2354.58,1205.42) 2390,1205.42 v1(2390,2018)
S_REG: Q6.1 R35.1 U7.10 | length 2394.5
  Top Layer w22: v1@1273,1559.81 1273,1560 1296,1583 v1(1468,1583) ; U7.10@1578,1766 v1(1638,1766)
  Bottom Layer w22: R35.1@764.33,210 cw(c764.33,199.73) R35.1@774.6,199.73 ; R35.1@772.33,210 793.1,210 ; 810,188.77 810,1395 cw(c875,1395) 875,1460 1230.69,1460 ccw(c1230.69,1502.31) 1273,1502.31 v1(1273,1559.57) ; v1(1468,1583) ccw(c1468,1645) 1530,1645 1530,1716.51 cw(c1579.49,1716.51) 1579.49,1766 v1(1638,1766)
S_SENS: R55.2 U7.28 U10.1 | length 1730.5
  Top Layer w22: R55.2@981,1840 980.41,1839.41 980.41,1714.81 U10.1@980.82,1714.4 1024.6,1714.4 cw(c1024.6,1697) 1042,1697 1042,1635 ccw(c1068,1635) 1068,1609 1152,1609 cw(c1152,1585) 1176,1585 1176,1537.98 ccw(c1223.98,1537.98) 1223.98,1490 1512.93,1490 ccw(c1512.93,1507.07) 1530,1507.07 1530,1517 cw(c1547,1517) 1547,1534 v1(1652,1534) ; v1(1962,1595) 2126,1595 ccw(c2126,1623) 2154,1623 2154,1692.52 cw(c2177.48,1692.52) 2177.48,1716 U7.28@2247.29,1716
  Bottom Layer w22: v1(1652,1534) 1747,1534 ccw(c1747,1574) 1787,1574 cw(c1808,1574) 1808,1595 v1(1962,1595)
SCL_: R5.1 U6.6 U7.36 | length 2418.2
  Top Layer w20: U7.36@2242,2118 v1@2307,2118
  Bottom Layer w20: v1(2100,160) 2290.6,160 ccw(c2290.6,237.4) 2368,237.4 2368,490 2450,572 2450,2083.05 ccw(c2416.05,2083.05) 2416.05,2117 v1(2308,2117)
SDA_: R4.1 U6.1 U7.33 | length 2295.2
  Top Layer w20: U7.33@2242,1968 v1@2421,1968
  Bottom Layer w20: v1(2020,161) 2020,174 cw(c2040,174) 2040,194 2259,194
  Bottom Layer w22: 2259,194 ccw(c2259,275) 2339,262.31 ccw(c2259,275) 2340,275 2340,501.6 2421,582.6 v1(2421,1967)
SENSE#: R40.1 R42.1 U10.3 | length 2
  Top Layer w12: R40.1@977,1570 R40.1@979,1570
SOFT_P: C25.1 R24.1 SW2.1 U7.16 | length 1650.6
  Top Layer w20: U7.16@1737.67,1528.63 ccw(c1737.67,1530.96) 1740,1530.96 v1(1740,1591)
  Bottom Layer w20: 858,2347 1409,2347 cw(c1409,2302) 1454,2302 1454,1963 ccw(c1492,1963) 1492,1925 1704,1925 cw(c1704,1889) 1740,1889 v1(1740,1591)
  other v1: 786,2486 812,2486 838,2486 864,2486
TS: R29.2 U8.1 | length 117.7
  Top Layer w22: v1(837,2083) 837,2082.4 U8.1@868.82,2082.4
  Bottom Layer w22: v1@838,2083 849.65,2083 cw(c849.65,2062.65) 870,2062.65 R29.2@870,2021
TX: J1.2 P6.1 U7.35 | length 2669.7
  Top Layer w22: P6.1@1122.25,1049 1122.25,1177 cw(c1150.25,1177) 1150.25,1205 1993.51,1205 ccw(c1993.51,1228.49) 2017,1228.49 v1(2017,1287) 2017,1298 cw(c2042,1298) 2042,1323 2118,1323 cw(c2118,1303) J1.2@2138,1303 ; U7.35@2244,2066 cw(c2244,2068) 2242,2068 2245,2071 v1(2362,2071)
  Bottom Layer w20: v1(2017,1287) 2017,1226.92 ccw(c2043.37,1226.92) 2043.37,1200.55 2329.83,1200.55 ccw(c2329.83,1232.22) 2361.5,1232.22 2361.5,2005.76 2361.19,2006.07 2361.19,2029.93 2361.5,2030.24 2361.5,2070.5 v1(2362,2071)
VBAT: C80.1 Q9.2 U9.6
  other v1: 356,2041
VBUS: C18.1 C19.1 C79.1 C#4.1 C#5.1 J2.3 P2.1 R37.2 R40.2 R57.1 U8.6 U9.8 U15.1 | length 3997.9
  Top Layer w22: C79.1@529,1612 C79.1@529,1618 ; U8.6@973.58,2082 C19.1@1026,2082 ; 1121.34,2082 cw(c1121.34,2074) 1129.34,2074 ; v1@1185,497 1187,495 v1@1187,120 ; v1(1567,90) 1567,89.6 U15.1@1614.18,89.6
  Top Layer w40: J2.3@436.08,410.5 v1(436.08,474.91) ; v1@1007,1147 1007,1001 ccw(c1054,1001) 1054,954 1090.15,954 cw(c1090.15,893.15) 1151,893.15 1151,635 ccw(c1205,635) 1205,581 v1(1272,581) ; 1189,2069 1189,1946 1269.35,1865.64 v1@1269.35,1811
  Bottom Layer w22: v1@1193.7,113 1566,113
  Bottom Layer w40: v1(436.08,474.91) 436.08,808 cw(c536.08,808) 536.08,908 669.65,908 ccw(c669.65,960.35) 722,960.35 v1(722,1173) ; v1(1008,1152) 1217,1152 ccw(c1217,1252) 1317,1252 1317,1766 ccw(c1272,1766) v1(1272,1811) ; v1(1186,497) 1231,542 R57.1@1231,580 v1@1272,580
  other v1: 1188,113
VDD#: C#3.1 LED1.5 U15.5 | length 1082.9
  Top Layer w22: LED1.5@1234.46,708 1327,708 1346,689 1346,556 1324,534 1253.4,534 1216,496.6 1216,137 1264,89 C#3.1@1458,89 1458,89.6 U15.5@1511.82,89.6
VIN: C11.1 C26.1 C27.1 C40.1 L2.1 R4#.2 U1.5 U2.7 U2.8 U9.7 | length 1008.4
  Top Layer w22: C27.1@722,46 C27.1@722,48
  Top Layer w40: 520,580 520,404 ccw(c546,404) 546,378 L2.1@584.52,378
  Bottom Layer w40: v1(352,581) 352,142.54 ccw(c426.54,142.54) 426.54,68 v1(539,68) R4#.2@622,68
VSNS: R37.1 R38.2 U9.3 | length 147
  Top Layer w18: U9.3@764.97,1737 R37.1@839,1737
  Top Layer w40: R37.1@839,1735 R38.2@912,1735
pads on no net: J1.MP5 J1.MP6 J1.MP7 LED1.1 LED1.3 LED1.4 U2.3 U4.4 U4.12 U6.3 U6.4 U7.4 U7.5 U7.6 U7.9 U7.14 U7.17 U7.18 U7.19 U7.20 U7.21 U7.22 U7.23 U7.24 U7.29 U9.1 U13.5 U13.6 U13.7 U15.4

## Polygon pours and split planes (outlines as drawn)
GND on Bottom Layer "Bottom Layer-GND" (hatched 45Degree grid 20 track 8, remove dead copper, pour order 0): -170,262 -170,2240 49,2240 49,2448 1414,2448 1414,2202 2395,2202 2395,2448 2485,2448 2485,80 49,80 49,262
GND on Top Layer "Bottom Layer-GND" (hatched 45Degree grid 20 track 8, remove dead copper, pour order 2): -163,274 -163,2252 56,2252 56,2460 1421,2460 1421,2214 2314,2214 2314,2460 2492,2460 2492,92 56,92 56,274

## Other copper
Top Layer:
  rectangle net 3V3_SENS: 860,8 998,59
  rectangle net GND: 1271,111 1477,508
  rectangle net GND: 1440,112 1638,145
  rectangle net 3V3_SENS: 947,13 1008,68
  rectangle net 3V3: 1651,43 1710,127
  rectangle net 3V3_Audio: 1860,111 1977,224
  rectangle net GND: 1780,6 1992,104
  rectangle net 3V3: 1033,1794 1207,1868
  rectangle net 3V3: 1113,1691 1241,1852
  rectangle net VBUS: 1002,2054 1209,2100
  rectangle net BATT_IN: 637,2008 818,2158
  rectangle net BATT_IN: 637,2027 896,2063
  rectangle net #OUT_MIC: 1985,537 2125,717
  rectangle net GND: 1039,2197 1195,2505
  rectangle net VIN: 481,1702 565,1720
  rectangle net VBAT: 477,1728 565,1746
  rectangle net VIN: 245,9 310,1720
  rectangle net VIN: 245,1678 494,1720
  rectangle net VIN: 283,53 693,94
  rectangle net VIN: 280,553 715,608
  rectangle net P_D: 695,399 754,477
  rectangle net 3V3: 803,539 1031,558
  rectangle net 3V3: 989,445 1121,610
  rectangle net 3V3: 782,445 1022,479
  rectangle net 3V3: 782,553 1043,610
  rectangle net GND: 505,1753 604,1905
  rectangle net GND: 389,1788 535,1905
  rectangle net GND: 333,1788 394.35,1987
  rectangle net VBAT: 250,1994 383,2045
  rectangle net VBAT: 244,1728 316,2045
  rectangle net VBAT: 245,1728 498,1777
  rectangle net IN-: 402,1948 497,2007
  rectangle net 3V3_SENS: 947,8 1770,29
  rectangle net GND: 813,178 860,222
  rectangle net GND: 833,173 1012,266
  rectangle net GND: 370,107 1012,183
  rectangle net VBUS: 917,1099 1030,1537
  rectangle net VBUS: 846,1099 939,1626
  rectangle net VBUS: 694,1099 874,1669
  rectangle net VBUS: 502,1406 708,1695
  rectangle net AC_LINE: 335,1008 611,1373
  rectangle net GND: 1041,1272 1705,1466
  rectangle net SENSE#: 997,1545 1032,1608
  rectangle net SENSE#: 947,1545 1024,1655
  rectangle net 3V3: 1113,1668 1435,1783
  rectangle net 3V3: 1060,1665 1435,1691
  rectangle net GND: 1041,1272 1145,1591
  rectangle net GND: 2083,20 2148,131
  rectangle net GND: 1987,6 2327,25
  rectangle net GND: 1668,369 2076,444
  rectangle net #15-P: 1889,452 2121,529
  rectangle net GND: 678,265 769,294
  rectangle net VIN: 283,9 828.33,62
  rectangle net GND: 370,220 487,357
  rectangle net GND: 370,109 665,270
  rectangle net GND: 765,88 849,140
  rectangle net 3V3_Audio: 776,273 928,330
  rectangle net C_VIN: 542,285 670,350
  rectangle net C_VIN: 619,302 725,392
  rectangle net GND: 1957,60 2130,97
  rectangle net GND: 104,2192 1195,2355
  rectangle net GND: 1631,369 1871,610
  rectangle net 3V3: 1644,2018 1684,2182
  rectangle net 3V3: 1400,2145 1684,2182
  rectangle net GND: 1668,1615 2073,1890
  rectangle net GND: 1676,1297 1705,1890
  rectangle net GND: 1098,2198 2290,2241
  rectangle net #_OUT_MIC: 1955,292 2004,360
  rectangle net NetR6_1: 2273,357 2395,425
  rectangle net NetC9_2: 2272,201 2345,349
  rectangle net #OUT_MIC: 2114,203 2241,286
  rectangle net OUT_MIC: 1779,111 1852,253
  rectangle net NetC8_2: 1783,289 1947,359
  rectangle net #_OUT_MIC: 1955,291 2066,360
  rectangle net SCL_: 2155,108 2193,175
  rectangle net SCL_: 2083,138 2190,175
  rectangle net SDA_: 2000,105 2076,175
  rectangle net GND: 531,2331 754,2506
  rectangle net SOFT_P: 769,2370 1025,2505
Bottom Layer:
  rectangle net GND: 830,50 1538,93
  rectangle net VBUS: 1554,73 1858,137
  rectangle net GND: 2257,5 2441,134
  rectangle net GND: 2200,94 2423,141
  rectangle net VBAT: 341,2024 398,2092
  rectangle net A_REG: 585,276 656,530
  rectangle net S_REG: 728,127 820,257
  rectangle net #_OUT_MIC: 2015,303 2067,578
  rectangle net GND: 2385,5 2454,398
  rectangle net 3V3: 2100,1597 2234,1661
  rectangle net GND: 663,270 752,419
  rectangle net 3V3_SENS: 1914,49 1989,236
  rectangle net GND: 830,2 1859,64
  rectangle net 3V3_SENS: 1914,13 2244,83
  rectangle net GND: 830,69 882,532
  rectangle net GND: 261,1578 1173,1961
  rectangle net GND: 1811,248 2004,488
  rectangle net GND: 239,2315 332,2508
  rectangle net GND: 10,2304 86,2385
  rectangle net GND: 10,1621 332,2509
  rectangle net 3V3: 1398,744 1436,2182
  rectangle net GND: 2388,320 2450,360
  rectangle net 3V3: 2100,1660 2285,2063
  rectangle net 3V3: 1596,2001 2279,2063
  rectangle net GND: 1595,2075 1693,2223
  rectangle net NetR2_1: 2132,302 2212,373
  rectangle net NetR2_1: 2075,302 2141,455
  rectangle net #_OUT_MIC: 1984,553 2114,699
  rectangle net SCL_: 2078,104 2147,176
  rectangle net SDA_: 2000,104 2068,176
  rectangle net SOFT_P: 768,2337 1036,2506
  rectangle net BATT_IN: 349,2105 729,2509

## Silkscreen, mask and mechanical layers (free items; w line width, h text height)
Top Overlay:
  drawing of 13 lines, arcs and shapes, not listed
  text "#" at 1090,2364 h80
  text "#" at 1002,2107 h80
  text "#" at 1442,2074 h80
  text "#" at 787,2072 h80
  text "# >> 0.1uf" at -236,1989.06 h80
  text "#" at 1119,1731 h80
  text "#" at 447,1645 h80
  text "#" at 554,1577 h80
  text "AC_LINE" at 587,1099 h65 r90
  text "B_ADC" at 703.75,1099 h50 r90
  text "AC_Neutral" at 812,1099 h65 r90
  text "3V3" at 929,1099 h50 r90
  text "VBUS" at 1045,1099 h50 r90
  text "TX" at 1164.75,1099 h50 r90
  text "RX" at 1280.5,1099 h50 r90
  text "#O_MIC" at 1389,1099 h50 r90
  text "GND" at 1512,1099 h50 r90
  text "#" at 2185,624 h80
  text "#" at 546,589 h80
  text "#" at 933,588 h80
  text "#" at 2186,558 h80
  text "#" at 801,349 h80
  text "#" at 856,333 h80
  text "#" at 1970,182 h80
  text "#" at 1947,115 h80
  text "#" at 1087,108 h80 r90
  text "#" at 680.63,19 h80 r90
Bottom Overlay:
  drawing of 3088 lines, arcs and shapes, not listed
  text "#" at 230,2213 h80
  text "#" at 2287,1614 h80
  text "#" at 2249,30 h80
  text "ZERO CARBON FOOTPRINT" at 1600,6 h38
Top Solder:
  rectangle: 1774,2002 1971,2224
Mechanical 13:
  lines w10: -240.16,231.28 0,231.28 0,-0.68 2515.98,-0.68 2515.98,2519 2273,2519 2273,2269 1553,2269 1553,2519 1089,2519 390,2519 0,2519 0,2287.03 -240.16,2287.03 -240.16,231.28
